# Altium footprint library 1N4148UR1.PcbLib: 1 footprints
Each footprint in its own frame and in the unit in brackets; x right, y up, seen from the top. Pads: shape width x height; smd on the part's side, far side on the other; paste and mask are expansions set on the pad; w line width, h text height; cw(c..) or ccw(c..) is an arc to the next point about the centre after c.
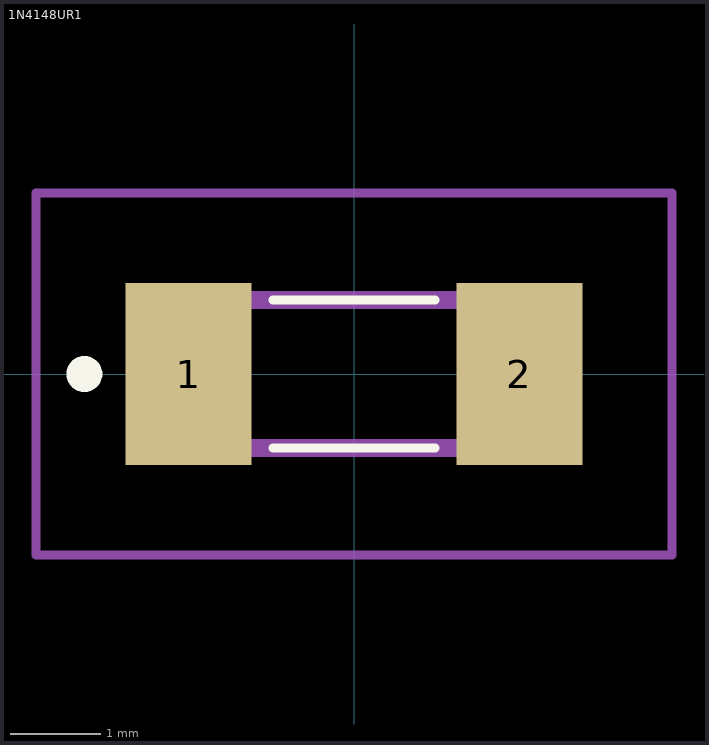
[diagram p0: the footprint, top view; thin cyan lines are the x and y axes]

## 1N4148UR1 [mm]
pads (2):
  rect 1.4x2.03 smd: 1(-1.84,0) 2(1.84,0)
Top Overlay:
  lines w0.1: -0.9,-0.825 0.9,-0.825 ; -0.9,0.825 0.9,0.825
  lines w0.2: -3,-0.1 cw(c-3,0) -3,0.1 ; -3,-0.1 -3,-0.1 ; -3,-0.1 ccw(c-3,0) -3,0.1 ; -3,0.1 -3,0.1
Mechanical 15:
  lines w0.2: -1.75,-0.825 1.75,-0.825 1.75,0.825 -1.75,0.825 -1.75,-0.825
Mechanical 20:
  lines w0.1: -3.54,-2.015 3.54,-2.015 3.54,2.015 -3.54,2.015 -3.54,-2.015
